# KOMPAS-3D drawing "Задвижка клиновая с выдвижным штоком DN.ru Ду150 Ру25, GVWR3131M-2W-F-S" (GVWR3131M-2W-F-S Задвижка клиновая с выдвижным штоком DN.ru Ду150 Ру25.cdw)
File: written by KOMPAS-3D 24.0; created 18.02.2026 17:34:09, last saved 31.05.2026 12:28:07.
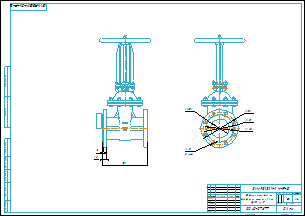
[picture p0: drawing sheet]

Document properties: art: D040-10012; Автор: R2D2; Форматы листов документа: A2; Полное имя файла: GVWR3131M-2W-F-S Задвижка клиновая с выдвижным штоком DN.ru Ду150 Ру25.m3d; Масса: 61; Наименование: Задвижка клиновая с выдвижным штоком DN.ru Ду150 Ру25; Количество листов документа: 1; Примечание: D040-07877

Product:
- Part/product: Задвижка клиновая с выдвижным штоком DN.ru Ду150 Ру25  | designation GVWR3131M-2W-F-S
    Масса: 61
    Раздел спецификации: Прочие изделия
    Примечание: D040-07877

Referenced files in E:\Работа\Зайцев\Для компаса\: чертеж DN.ru А3.cdt
Referenced files in E:\Работа\Зайцев\GVWR3131M-2W-F-S Задвижка клиновая 30нж64нж DN.ru  Ду50-150 Ру25\исходные данные\DN150\dn150\: GVWR3131M-2W-F-S Задвижка клиновая с выдвижным штоком DN.ru Ду150 Ру25.m3d
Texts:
  чертеж DN.ru А3.cdt
  Задвижка клиновая с
  выдвижным штоком DN.ru
  Ду150 Ру25
  GVWR3131M-2W-F-S
  Задвижка клиновая с выдвижным штоком DN.ru Ду150 Ру25
  GVWR3131M-2W-F-S Задвижка клиновая с выдвижным штоком DN.ru Ду150 Ру25
Dimensions and other numbers on the sheet: 1:4; 0; 1; 2; 61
